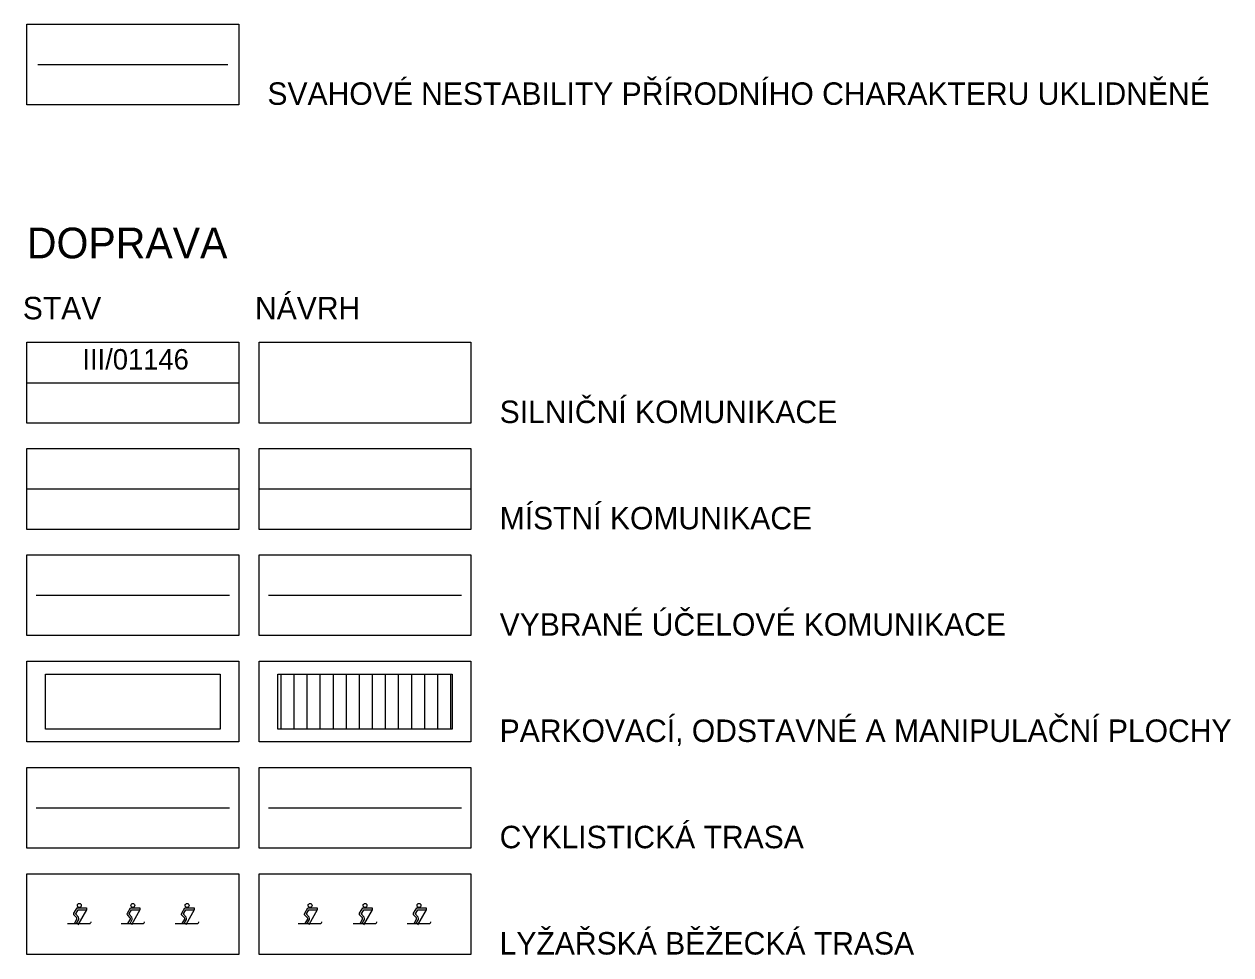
# Model space of a CAD drawing. Extents: x -439236 to -436242, y -1130161 to -1121098.
# Drawn here: x -439126 to -438536, y -1128539 to -1128084 of the extents above; entities that cross this region are included whole.
import ezdxf

# ---------------------------------------------------------------- set-up
doc = ezdxf.new("R2010")
doc.units = 0
for name, color, linetype in [('11811012_místní  komunikace_Stav', 7, 'Continuous'), ('11811022_místní  komunikace_Návrh', 7, 'Continuous'), ('11850012_silnice III třídy_Stav', 7, 'Continuous'), ('11850013_silnice III třídy_Stav', 7, 'Continuous'), ('Svahové nestability přírodního charakteru uklidněné', 7, 'Continuous'), ('Vrstva 1', 7, 'Continuous'), ('Vrstva 15', 7, 'Continuous'), ('Vrstva 23', 7, 'Continuous'), ('Vrstva 33', 7, 'Continuous'), ('Vrstva 35', 7, 'Continuous'), ('Vrstva 41', 7, 'Continuous'), ('Vrstva 43', 7, 'Continuous'), ('Vrstva 53', 7, 'Continuous'), ('Vrstva 61', 7, 'Continuous')]:
    doc.layers.add(name, color=color, linetype=linetype)

msp = doc.modelspace()

# ---------------------------------------------------------------- linework, layer by layer
at = {"layer": '11811012_místní  komunikace_Stav'}
msp.add_line((-439124.89, -1128311.2), (-439021.28, -1128311.2), dxfattribs=at)
at = {"layer": '11811022_místní  komunikace_Návrh'}
msp.add_line((-439011.28, -1128311.2), (-438907.66, -1128311.2), dxfattribs=at)
at = {"layer": '11850012_silnice III třídy_Stav'}
msp.add_line((-439124.89, -1128259.19), (-439021.28, -1128259.19), dxfattribs=at)
at = {"layer": 'Svahové nestability přírodního charakteru uklidněné'}
msp.add_lwpolyline([(-439119.5, -1128103.47), (-439026.67, -1128103.47)], dxfattribs=at)
at = {"layer": 'Vrstva 1'}
for points in [[(-439124.89, -1128083.72), (-439021.28, -1128083.72), (-439021.28, -1128083.72), (-439021.28, -1128123.22), (-439124.89, -1128123.22)], [(-439124.89, -1128239.43), (-439021.28, -1128239.43), (-439021.28, -1128239.43), (-439021.28, -1128278.94), (-439124.89, -1128278.94)], [(-439011.28, -1128239.43), (-438907.66, -1128239.43), (-438907.66, -1128239.43), (-438907.66, -1128278.94), (-439011.28, -1128278.94)], [(-439124.89, -1128291.45), (-439021.28, -1128291.45), (-439021.28, -1128291.45), (-439021.28, -1128330.96), (-439124.89, -1128330.96)], [(-439011.28, -1128291.45), (-438907.66, -1128291.45), (-438907.66, -1128330.96), (-439011.28, -1128330.96)], [(-439124.89, -1128343.47), (-439021.28, -1128343.47), (-439021.28, -1128343.47), (-439021.28, -1128382.97), (-439124.89, -1128382.97)], [(-439011.28, -1128343.47), (-438907.66, -1128343.47), (-438907.66, -1128382.97), (-439011.28, -1128382.97)], [(-439124.89, -1128395.49), (-439021.28, -1128395.49), (-439021.28, -1128395.49), (-439021.28, -1128434.99), (-439124.89, -1128434.99)], [(-439011.28, -1128395.49), (-438907.66, -1128395.49), (-438907.66, -1128434.99), (-439011.28, -1128434.99)], [(-439124.89, -1128447.51), (-439021.28, -1128447.51), (-439021.28, -1128447.51), (-439021.28, -1128487.01), (-439124.89, -1128487.01)], [(-439011.28, -1128447.51), (-438907.66, -1128447.51), (-438907.66, -1128487.01), (-439011.28, -1128487.01)], [(-439124.89, -1128499.52), (-439021.28, -1128499.52), (-439021.28, -1128499.52), (-439021.28, -1128539.03), (-439124.89, -1128539.03)], [(-439011.28, -1128499.52), (-438907.66, -1128499.52), (-438907.66, -1128539.03), (-439011.28, -1128539.03)]]:
    msp.add_lwpolyline(points, close=True, dxfattribs=at)
at = {"layer": 'Vrstva 15'}
msp.add_line((-439120.33, -1128363.22), (-439025.84, -1128363.22), dxfattribs=at)
at = {"layer": 'Vrstva 23'}
msp.add_line((-439006.72, -1128363.22), (-438912.22, -1128363.22), dxfattribs=at)
at = {"layer": 'Vrstva 33'}
msp.add_lwpolyline([(-439115.77, -1128401.79), (-439030.4, -1128401.79), (-439030.4, -1128428.69), (-439115.77, -1128428.69)], close=True, dxfattribs=at)
at = {"layer": 'Vrstva 35'}
msp.add_line((-439120.33, -1128467.26), (-439025.84, -1128467.26), dxfattribs=at)
at = {"layer": 'Vrstva 41'}
for p, q in [((-439000.5, -1128428.69), (-439000.5, -1128401.79)), ((-438994.12, -1128428.69), (-438994.12, -1128401.79)), ((-438987.74, -1128428.69), (-438987.74, -1128401.79)), ((-438981.35, -1128428.69), (-438981.35, -1128401.79)), ((-438974.97, -1128428.69), (-438974.97, -1128401.79)), ((-438968.58, -1128428.69), (-438968.58, -1128401.79)), ((-438962.2, -1128428.69), (-438962.2, -1128401.79)), ((-438955.82, -1128428.69), (-438955.82, -1128401.79)), ((-438949.43, -1128428.69), (-438949.43, -1128401.79)), ((-438943.05, -1128428.69), (-438943.05, -1128401.79)), ((-438936.66, -1128428.69), (-438936.66, -1128401.79)), ((-438930.28, -1128428.69), (-438930.28, -1128401.79)), ((-438923.9, -1128428.69), (-438923.9, -1128401.79)), ((-438917.51, -1128428.69), (-438917.51, -1128401.79))]:
    msp.add_line(p, q, dxfattribs=at)
msp.add_lwpolyline([(-439002.16, -1128401.79), (-438916.78, -1128401.79), (-438916.78, -1128428.69), (-439002.16, -1128428.69)], close=True, dxfattribs=at)
at = {"layer": 'Vrstva 43'}
msp.add_line((-439006.72, -1128467.26), (-438912.22, -1128467.26), dxfattribs=at)
at = {"layer": 'Vrstva 53'}
for p, q in [((-439100.37, -1128516.22), (-439095.8, -1128516.22)), ((-439074.21, -1128516.22), (-439069.63, -1128516.22)), ((-439047.65, -1128516.22), (-439043.08, -1128516.22)), ((-439099.87, -1128517.12), (-439095.8, -1128517.12)), ((-439073.7, -1128517.12), (-439069.63, -1128517.12)), ((-439047.15, -1128517.12), (-439043.08, -1128517.12))]:
    msp.add_line(p, q, dxfattribs=at)
for points in [[(-439101.63, -1128523.88), (-439100.43, -1128521.66), (-439100.43, -1128521.4), (-439100.48, -1128521.14), (-439101.74, -1128519.78), (-439101.92, -1128519.52), (-439101.94, -1128519.12), (-439101.89, -1128518.76), (-439100.37, -1128516.22)], [(-439095.8, -1128516.22), (-439095.8, -1128517.12), (-439099.93, -1128524.52)], [(-439075.46, -1128523.88), (-439074.26, -1128521.66), (-439074.26, -1128521.4), (-439074.31, -1128521.14), (-439075.57, -1128519.78), (-439075.75, -1128519.52), (-439075.78, -1128519.12), (-439075.72, -1128518.76), (-439074.21, -1128516.22)], [(-439069.63, -1128516.22), (-439069.63, -1128517.12), (-439073.76, -1128524.52)], [(-439048.91, -1128523.88), (-439047.71, -1128521.66), (-439047.71, -1128521.4), (-439047.76, -1128521.14), (-439049.02, -1128519.78), (-439049.2, -1128519.52), (-439049.22, -1128519.12), (-439049.17, -1128518.76), (-439047.65, -1128516.22)], [(-439043.08, -1128516.22), (-439043.08, -1128517.12), (-439047.21, -1128524.52)], [(-439100.61, -1128523.88), (-439099.53, -1128521.89), (-439099.53, -1128521.31), (-439099.65, -1128520.71), (-439101.03, -1128519.21), (-439101.04, -1128519.21), (-439101.04, -1128519.16), (-439101.03, -1128519.06), (-439099.87, -1128517.12)], [(-439074.44, -1128523.88), (-439073.36, -1128521.89), (-439073.36, -1128521.31), (-439073.48, -1128520.71), (-439074.87, -1128519.21), (-439074.87, -1128519.21), (-439074.87, -1128519.16), (-439074.86, -1128519.06), (-439073.7, -1128517.12)], [(-439047.89, -1128523.88), (-439046.81, -1128521.89), (-439046.81, -1128521.31), (-439046.93, -1128520.71), (-439048.31, -1128519.21), (-439048.32, -1128519.21), (-439048.32, -1128519.16), (-439048.31, -1128519.06), (-439047.15, -1128517.12)], [(-439105.02, -1128523.88), (-439094.39, -1128523.88), (-439093.98, -1128523.76), (-439093.7, -1128523.55), (-439093.5, -1128523.22), (-439093.49, -1128522.96)], [(-439078.85, -1128523.88), (-439068.23, -1128523.88), (-439067.81, -1128523.76), (-439067.53, -1128523.55), (-439067.34, -1128523.22), (-439067.32, -1128522.96)], [(-439052.3, -1128523.88), (-439041.67, -1128523.88), (-439041.26, -1128523.76), (-439040.98, -1128523.55), (-439040.78, -1128523.22), (-439040.77, -1128522.96)]]:
    msp.add_lwpolyline(points, dxfattribs=at)
for centre in [(-439099.25, -1128514.98), (-439073.09, -1128514.98), (-439046.53, -1128514.98)]:
    msp.add_circle(centre, 0.951, dxfattribs=at)
at = {"layer": 'Vrstva 61'}
for p, q in [((-438987.48, -1128516.22), (-438982.91, -1128516.22)), ((-438960.59, -1128516.22), (-438956.02, -1128516.22)), ((-438934.2, -1128516.22), (-438929.63, -1128516.22)), ((-438986.98, -1128517.12), (-438982.91, -1128517.12)), ((-438960.08, -1128517.12), (-438956.02, -1128517.12)), ((-438933.7, -1128517.12), (-438929.63, -1128517.12))]:
    msp.add_line(p, q, dxfattribs=at)
for points in [[(-438988.74, -1128523.88), (-438987.54, -1128521.66), (-438987.54, -1128521.4), (-438987.59, -1128521.14), (-438988.85, -1128519.78), (-438989.03, -1128519.52), (-438989.05, -1128519.12), (-438989, -1128518.76), (-438987.48, -1128516.22)], [(-438982.91, -1128516.22), (-438982.91, -1128517.12), (-438987.04, -1128524.52)], [(-438961.85, -1128523.88), (-438960.64, -1128521.66), (-438960.64, -1128521.4), (-438960.69, -1128521.14), (-438961.95, -1128519.78), (-438962.13, -1128519.52), (-438962.16, -1128519.12), (-438962.11, -1128518.76), (-438960.59, -1128516.22)], [(-438956.02, -1128516.22), (-438956.02, -1128517.12), (-438960.15, -1128524.52)], [(-438935.46, -1128523.88), (-438934.26, -1128521.66), (-438934.26, -1128521.4), (-438934.31, -1128521.14), (-438935.57, -1128519.78), (-438935.75, -1128519.52), (-438935.77, -1128519.12), (-438935.72, -1128518.76), (-438934.2, -1128516.22)], [(-438929.63, -1128516.22), (-438929.63, -1128517.12), (-438933.76, -1128524.52)], [(-438987.72, -1128523.88), (-438986.64, -1128521.89), (-438986.64, -1128521.31), (-438986.76, -1128520.71), (-438988.14, -1128519.21), (-438988.15, -1128519.21), (-438988.15, -1128519.16), (-438988.14, -1128519.06), (-438986.98, -1128517.12)], [(-438960.83, -1128523.88), (-438959.75, -1128521.89), (-438959.74, -1128521.31), (-438959.87, -1128520.71), (-438961.25, -1128519.21), (-438961.26, -1128519.2), (-438961.26, -1128519.16), (-438961.25, -1128519.06), (-438960.08, -1128517.12)], [(-438934.44, -1128523.88), (-438933.36, -1128521.89), (-438933.36, -1128521.31), (-438933.48, -1128520.71), (-438934.86, -1128519.21), (-438934.87, -1128519.21), (-438934.87, -1128519.16), (-438934.86, -1128519.06), (-438933.7, -1128517.12)], [(-438992.13, -1128523.88), (-438981.5, -1128523.88), (-438981.08, -1128523.76), (-438980.81, -1128523.55), (-438980.61, -1128523.22), (-438980.6, -1128522.96)], [(-438965.24, -1128523.88), (-438954.61, -1128523.88), (-438954.19, -1128523.76), (-438953.91, -1128523.55), (-438953.72, -1128523.22), (-438953.7, -1128522.96)], [(-438938.85, -1128523.88), (-438928.22, -1128523.88), (-438927.8, -1128523.76), (-438927.53, -1128523.55), (-438927.33, -1128523.22), (-438927.31, -1128522.96)]]:
    msp.add_lwpolyline(points, dxfattribs=at)
for centre in [(-438986.36, -1128514.98), (-438959.47, -1128514.98), (-438933.08, -1128514.98)]:
    msp.add_circle(centre, 0.951, dxfattribs=at)

# ---------------------------------------------------------------- texts
at = {"layer": '11850013_silnice III třídy_Stav'}
msp.add_text('III/01146', height=10, dxfattribs=at).set_placement((-439097.73, -1128252.74))
at = {"layer": 'Vrstva 1'}
for s, height, p in [('SVAHOVÉ NESTABILITY PŘÍRODNÍHO CHARAKTERU UKLIDNĚNÉ', 11, (-439007.23, -1128123.22)), ('DOPRAVA', 15, (-439124.89, -1128198.31)), ('NÁVRH', 11, (-439013.3, -1128228.18)), ('STAV', 11, (-439126.91, -1128228.18)), ('SILNIČNÍ KOMUNIKACE', 11, (-438893.61, -1128278.94)), ('MÍSTNÍ KOMUNIKACE ', 11, (-438893.61, -1128330.96)), ('VYBRANÉ ÚČELOVÉ KOMUNIKACE', 11, (-438893.61, -1128382.97)), ('PARKOVACÍ, ODSTAVNÉ A MANIPULAČNÍ PLOCHY', 11, (-438893.61, -1128434.99)), ('CYKLISTICKÁ TRASA', 11, (-438893.61, -1128487.01)), ('LYŽAŘSKÁ BĚŽECKÁ TRASA', 11, (-438893.61, -1128539.03))]:
    msp.add_text(s, height=height, dxfattribs=at).set_placement(p)

doc.saveas('drawing.dxf')
